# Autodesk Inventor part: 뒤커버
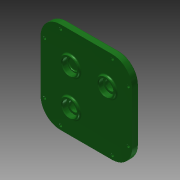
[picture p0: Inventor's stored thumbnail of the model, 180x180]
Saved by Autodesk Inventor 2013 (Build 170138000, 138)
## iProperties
Created: 2016-12
Part Number: 뒤커버
Material: 알루미늄 6061
Document SubType Name: Modeling
Designer: mduedu
Density: 2.71 g/cm^3
Mass: 485.373 g
Surface Area: 454.562 cm^2
Volume: 179.104 cm^3
Author: mduedu
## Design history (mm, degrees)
sketch "스케치1"
  geometry: L1 (-46, 42)-(-46, -36); L2 (-16, 72)-(62, 72); L3 (92, 42)-(92, -36); L4 (62, -66)-(-16, -66); A1 r 30 centre (-16, -36) between (-46, -36) and (-16, -66); A2 r 30 centre (62, 42) between (92, 42) and (62, 72); A3 r 30 centre (62, -36) between (62, -66) and (92, -36); A4 r 30 centre (-16, 42) between (-16, 72) and (-46, 42); 1 further point
  constraints: 8 end point, 8 point on circle, 8 tangent, 4 centre point, 3 equal radius, 2 perpendicular, 1 horizontal, 1 vertical
  dimensions: "d80" = 30 radius of A2; "d81" = 138 distance between parallel lines of L4 L2; "d82" = 92 distance from line of L3 point (0, 0); "d114" = 46 distance from line of L1 point (0, 0); "d115" = 72 distance from line of L2 point (0, 0)
extrude "돌출1" new body sketch "스케치1" distance "d3" = 10; taper "d4" = 0 deg
sketch "스케치2"
  geometry: C1 r 14 at (0, 26); 1 further point
  constraints: 1 centre point, 1 vertical alignment
  dimensions: "d5" = 28 diameter of C1; "d6" = 26 distance of C1.centre point (0, 0)
extrude "돌출2" join sketch "스케치2" distance "d7" = 3; taper "d8" = 0 deg
sketch "스케치3"
  geometry: C1 r 14 at (0, -28.87); C2 r 14 at (0, 26) reference; C3 r 14 at (54.87, 26); 1 further point
  constraints: 2 centre point, 1 horizontal alignment, 1 vertical alignment
  dimensions: "d9" = 28 diameter of C1; "d69" = 54.87 distance of C1.centre C2.centre; "d83" = 28 diameter of C3; "d84" = 54.87 distance of C3.centre C2.centre
extrude "돌출3" join sketch "스케치3" distance "d11" = 3; taper "d12" = 0 deg
hole "구멍1" diameter "d15" = 22; stored, may be unused: countersink angle "d19" = 90 deg, drill point angle "d21" = 0 deg; dims "d13" = 10, "d14" = 10, "d16" = 6, "d17" = 4, "d18" = 2, "d20" = 7
hole "구멍2" diameter "d24" = 18; stored, may be unused: countersink angle "d28" = 90 deg, drill point angle "d30" = 0 deg; dims "d22" = 10, "d23" = 10, "d25" = 6, "d26" = 4, "d27" = 2, "d29" = 1
hole "구멍3" diameter "d33" = 22; stored, may be unused: countersink angle "d37" = 90 deg, drill point angle "d39" = 0 deg; dims "d31" = 10, "d32" = 10, "d34" = 6, "d35" = 4, "d36" = 2, "d38" = 7
hole "구멍7" diameter "d87" = 22; stored, may be unused: countersink angle "d91" = 90 deg, drill point angle "d93" = 0 deg; dims "d85" = 10, "d86" = 10, "d88" = 6, "d89" = 4, "d90" = 2, "d92" = 7
sketch "스케치4"
  geometry: C1 r 14 at (0, -28.87) reference; C2 r 18 at (0, -28.87); C3 r 14 at (-54.87, 26) reference; C4 r 18 at (-54.87, 26); 1 further point
  constraints: 2 centre point, 2 coincident
  dimensions: "d40" = 36 diameter of C2; "d94" = 36 diameter of C4
extrude "돌출4" join sketch "스케치4" distance "d41" = 4; taper "d42" = 0 deg
hole "구멍4" diameter "d45" = 22; stored, may be unused: countersink angle "d49" = 90 deg, drill point angle "d51" = 0 deg; dims "d43" = 10, "d44" = 10, "d46" = 6, "d47" = 4, "d48" = 2, "d50" = 7
hole "구멍8" diameter "d97" = 22; stored, may be unused: countersink angle "d101" = 90 deg, drill point angle "d103" = 0 deg; dims "d95" = 10, "d96" = 10, "d98" = 6, "d99" = 4, "d100" = 2, "d102" = 7
hole "구멍5" diameter "d54" = 15; stored, may be unused: countersink angle "d58" = 90 deg, drill point angle "d60" = 0 deg; dims "d52" = 10, "d53" = 10, "d55" = 6, "d56" = 4, "d57" = 2, "d59" = 7
hole "구멍9" diameter "d106" = 15; stored, may be unused: countersink angle "d110" = 90 deg, drill point angle "d112" = 0 deg; dims "d104" = 10, "d105" = 10, "d107" = 6, "d108" = 4, "d109" = 2, "d111" = 7
fillet "모깎기1" dims "d61" = 0.3
fillet "모깎기2" dims "d62" = 2
chamfer "모따기1" distance "d63" = 1; stored, may be unused: second distance "d64" = 2, angle "d65" = 45 deg
fillet "모깎기3" dims "d66" = 2
fillet "모깎기4" dims "d67" = 2
fillet "모깎기5" dims "d68" = 2
sketch "스케치5"
  geometry: L1 (-62, 72)-(16, 72) reference; L2 (-92, -36)-(-92, 42) reference; L3 (16, -66)-(-62, -66) reference; L4 (46, 42)-(46, -36) reference; L5 (16, 66)-(-62, 66); L6 (-86, 42)-(-86, -36); L7 (-62, -60)-(16, -60); L8 (40, -36)-(40, 42); A1 r 30 centre (-62, 42) between (-62, 72) and (-92, 42) reference; A2 r 30 centre (-62, -36) between (-92, -36) and (-62, -66) reference; A3 r 30 centre (16, -36) between (16, -66) and (46, -36) reference; A4 r 30 centre (16, 42) between (46, 42) and (16, 72) reference; A5 r 24 centre (-62, 42) between (-62, 66) and (-86, 42); A6 r 24 centre (-62, -36) between (-86, -36) and (-62, -60); A7 r 24 centre (16, -36) between (16, -60) and (40, -36); A8 r 24 centre (16, 42) between (40, 42) and (16, 66)
  constraints: 8 end point, 8 point on circle, 4 centre point, 7 other
  dimensions: "d113" = 6 distance between parallel lines of L6 L2
sketch "스케치6"
  geometry: L1 (16, 66)-(-62, 66) reference; L2 (40, -36)-(40, 42) reference; L3 (-62, -60)-(16, -60) reference; L4 (-86, 42)-(-86, -36) reference; A1 r 24 centre (16, 42) between (40, 42) and (16, 66) reference; A2 r 24 centre (16, -36) between (16, -60) and (40, -36) reference; A3 r 24 centre (-62, -36) between (-86, -36) and (-62, -60) reference; A4 r 24 centre (-62, 42) between (-62, 66) and (-86, 42) reference; 8 further points
  constraints: 8 coincident
hole "구멍6" sketch "스케치6" at (-62, 66), (-86, 42), (-86, -36), (-62, -60), (16, -60), (40, -36), (40, 42), (16, 66) diameter "d71" = 4.5; stored, may be unused: countersink angle "d75" = 90 deg, drill point angle "d77" = 0 deg; dims "d72" = 6, "d73" = 8, "d74" = 4.6, "d76" = 8
node "솔리드1"
